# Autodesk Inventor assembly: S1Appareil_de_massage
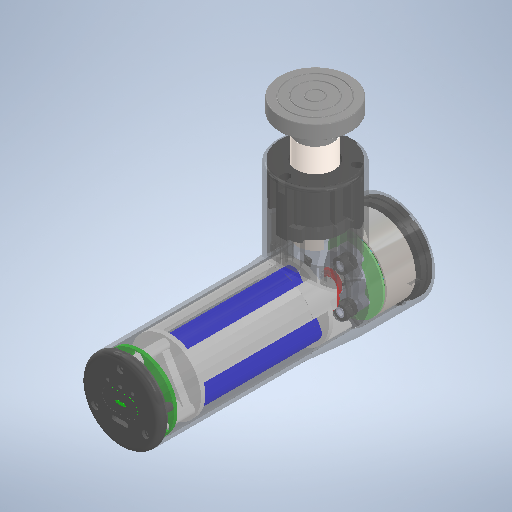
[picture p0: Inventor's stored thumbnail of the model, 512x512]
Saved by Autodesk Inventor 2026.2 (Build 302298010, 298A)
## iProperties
Created: 1601-01
Part Number: S1Appareil_de_massage
Document SubType Name: Assembly
Designer: mel
Author: mel
Part Number: Appareil_de_massage
Sending System: SOLIDWORKS 2023
Last Saved Date: 2025-04-02
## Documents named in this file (18)
- C:\Users\mel\Downloads\18256-itec-20250709t050547z-1-001 (1)\ITEC\Ressources\ITEC00_SW_Appareil_de_massage\S1Appareil_de_massage\S1Appareil_de_massage\S1Appareil_de_massage.iam
- C:\Users\mel\Downloads\18256-itec-20250709t050547z-1-001 (1)\ITEC\Ressources\ITEC00_SW_Appareil_de_massage\S1Appareil_de_massage\S1Appareil_de_massage\S1Bati.ipt
- C:\Users\mel\Downloads\18256-itec-20250709t050547z-1-001 (1)\ITEC\Ressources\ITEC00_SW_Appareil_de_massage\S1Appareil_de_massage\S1Appareil_de_massage\S1Capot_Haut.ipt
- C:\Users\mel\Downloads\18256-itec-20250709t050547z-1-001 (1)\ITEC\Ressources\ITEC00_SW_Appareil_de_massage\S1Appareil_de_massage\S1Appareil_de_massage\S1Support_Chemise.ipt
- C:\Users\mel\Downloads\18256-itec-20250709t050547z-1-001 (1)\ITEC\Ressources\ITEC00_SW_Appareil_de_massage\S1Appareil_de_massage\S1Appareil_de_massage\S1Chemise.ipt
- C:\Users\mel\Downloads\18256-itec-20250709t050547z-1-001 (1)\ITEC\Ressources\ITEC00_SW_Appareil_de_massage\S1Appareil_de_massage\S1Appareil_de_massage\S1Piston.ipt
- C:\Users\mel\Downloads\18256-itec-20250709t050547z-1-001 (1)\ITEC\Ressources\ITEC00_SW_Appareil_de_massage\S1Appareil_de_massage\S1Appareil_de_massage\S1Bielle.ipt
- C:\Users\mel\Downloads\18256-itec-20250709t050547z-1-001 (1)\ITEC\Ressources\ITEC00_SW_Appareil_de_massage\S1Appareil_de_massage\S1Appareil_de_massage\S1Manivelle.ipt
- C:\Users\mel\Downloads\18256-itec-20250709t050547z-1-001 (1)\ITEC\Ressources\ITEC00_SW_Appareil_de_massage\S1Appareil_de_massage\S1Appareil_de_massage\S1Cylindre_bloc.ipt
- C:\Users\mel\Downloads\18256-itec-20250709t050547z-1-001 (1)\ITEC\Ressources\ITEC00_SW_Appareil_de_massage\S1Appareil_de_massage\S1Appareil_de_massage\S1BrushlessStator_Moteur.ipt
- C:\Users\mel\Downloads\18256-itec-20250709t050547z-1-001 (1)\ITEC\Ressources\ITEC00_SW_Appareil_de_massage\S1Appareil_de_massage\S1Appareil_de_massage\S1BrushlessStator Assembly.iam
- C:\Users\mel\Downloads\18256-itec-20250709t050547z-1-001 (1)\ITEC\Ressources\ITEC00_SW_Appareil_de_massage\S1Appareil_de_massage\S1Appareil_de_massage\S1BrushlessAxe_moteur.ipt
- C:\Users\mel\Downloads\18256-itec-20250709t050547z-1-001 (1)\ITEC\Ressources\ITEC00_SW_Appareil_de_massage\S1Appareil_de_massage\S1Appareil_de_massage\S1Capot_moteur.ipt
- C:\Users\mel\Downloads\18256-itec-20250709t050547z-1-001 (1)\ITEC\Ressources\ITEC00_SW_Appareil_de_massage\S1Appareil_de_massage\S1Appareil_de_massage\S1Support_Batterie.ipt
- C:\Users\mel\Downloads\18256-itec-20250709t050547z-1-001 (1)\ITEC\Ressources\ITEC00_SW_Appareil_de_massage\S1Appareil_de_massage\S1Appareil_de_massage\S1Batterie.ipt
- C:\Users\mel\Downloads\18256-itec-20250709t050547z-1-001 (1)\ITEC\Ressources\ITEC00_SW_Appareil_de_massage\S1Appareil_de_massage\S1Appareil_de_massage\S1Capot_Batterie.ipt
- C:\Users\mel\Downloads\18256-itec-20250709t050547z-1-001 (1)\ITEC\Ressources\ITEC00_SW_Appareil_de_massage\S1Appareil_de_massage\S1Appareil_de_massage\S1Carte_electronique.ipt
- C:\Users\mel\Downloads\18256-itec-20250709t050547z-1-001 (1)\ITEC\Ressources\ITEC00_SW_Appareil_de_massage\S1Appareil_de_massage\S1Appareil_de_massage\S1Tete_de_massage.ipt
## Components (19 placed, 19 different names)
1. Bati-1
2. Capot_Haut-1
3. Support_Chemise-1
4. Chemise-1
5. Piston-1
6. Bielle-1
7. Manivelle-1
8. Cylindre_bloc-1
9. Cylindre_bloc-2
10. Cylindre_bloc-3
11. BrushlessStator_Moteur-2
12. BrushlessStator Assembly-2 [sub-assembly]
13. BrushlessAxe_moteur-2
14. Capot_moteur-1
15. Support_Batterie-1
16. Batterie-1
17. Capot_Batterie-1
18. Carte_electronique-1
19. Tete_de_massage-1
